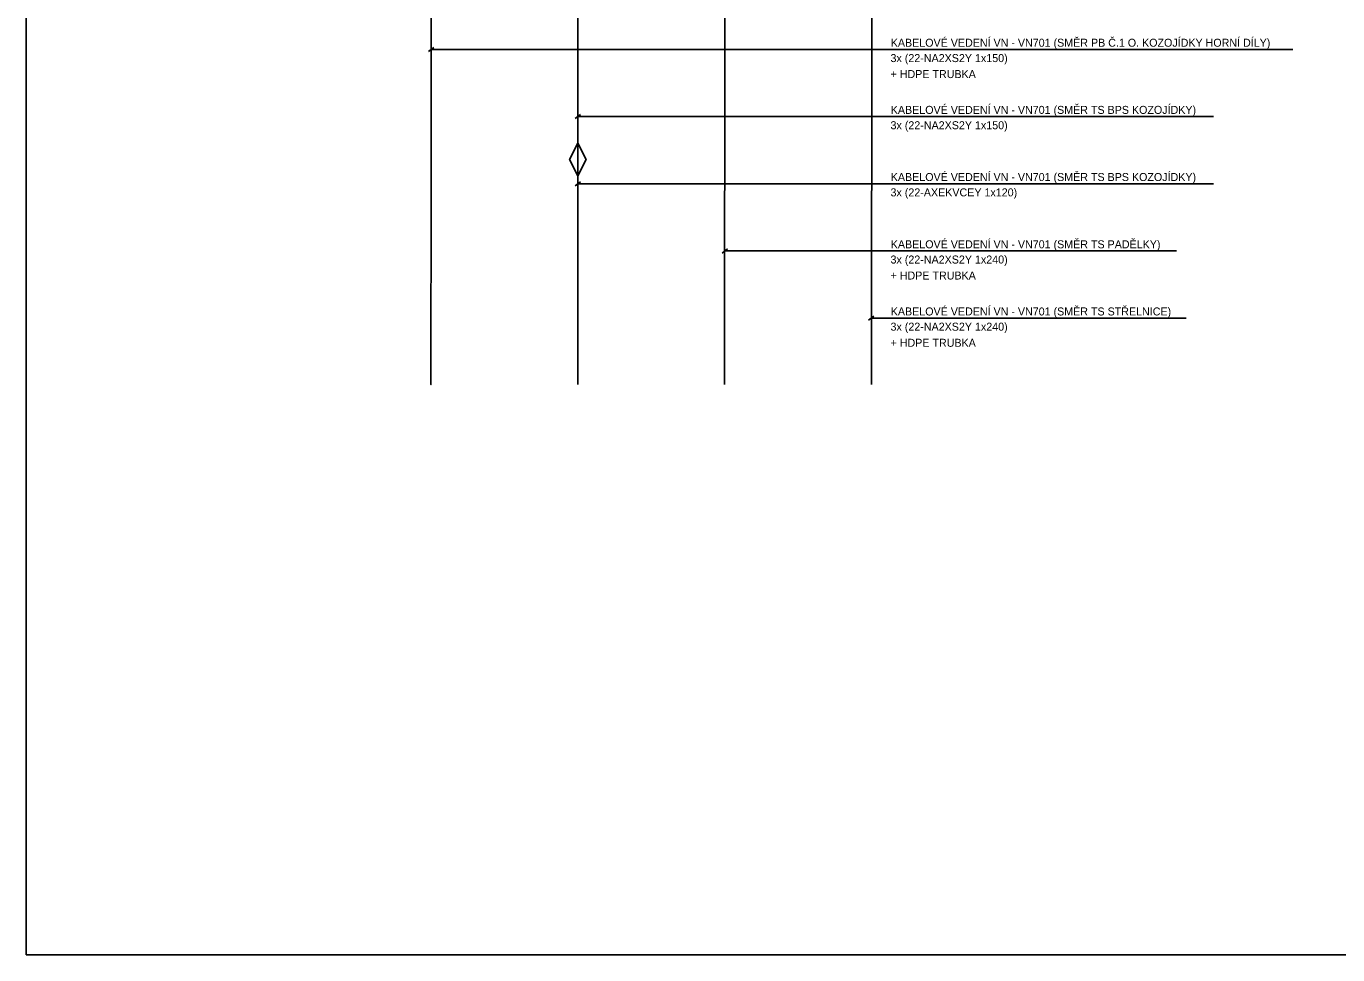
# Model space of a CAD drawing. Extents: x -540906 to -539838, y -1177786 to -1177461.
# Drawn here: x -540048 to -539943, y -1177785.8 to -1177711.4 of the extents above; entities that cross this region are included whole.
import ezdxf

# ---------------------------------------------------------------- set-up
doc = ezdxf.new("R2010")
doc.units = 0
for name, color, linetype in [('Implicitní', 7, 'Continuous'), ('KAB_SPOJKA_VN', 7, 'Continuous'), ('Kabel-nový', 7, 'Continuous'), ('Popisky', 7, 'Continuous'), ('TEXT-NORMAL', 7, 'Continuous'), ('TEXT-TUČNÝ-eon', 7, 'Continuous')]:
    doc.layers.add(name, color=color, linetype=linetype)

msp = doc.modelspace()

# ---------------------------------------------------------------- linework, layer by layer
at = {"layer": 'Implicitní'}
msp.add_lwpolyline([(-540047.95, -1177637.3), (-539837.95, -1177637.3), (-539837.95, -1177785.8), (-540047.95, -1177785.8)], close=True, dxfattribs=at)
at = {"layer": 'KAB_SPOJKA_VN'}
msp.add_lwpolyline([(-540003.79, -1177723.4), (-540004.45, -1177722.08), (-540003.79, -1177720.77), (-540003.13, -1177722.08)], close=True, dxfattribs=at)
at = {"layer": 'Kabel-nový'}
msp.add_lwpolyline([(-540015.53, -1177723.88), (-540015.56, -1177740.12), (-540015.56, -1177740.12)], dxfattribs=at)
at = {"layer": 'Popisky'}
for p, q in [((-540003.78, -1177704.05), (-540003.79, -1177722.08)), ((-539992.02, -1177704.05), (-539992.04, -1177740.12)), ((-539980.26, -1177704.05), (-539980.28, -1177740.12)), ((-540015.53, -1177704.15), (-540015.53, -1177723.88)), ((-540003.79, -1177722.08), (-540003.8, -1177740.12))]:
    msp.add_line(p, q, dxfattribs=at)
at = {"layer": 'TEXT-NORMAL'}
for p, q in [((-540015.74, -1177713.43), (-540015.32, -1177713.1)), ((-540015.53, -1177713.27), (-539946.54, -1177713.27)), ((-540004, -1177718.81), (-540003.58, -1177718.48)), ((-540003.79, -1177718.65), (-539952.89, -1177718.65)), ((-540004, -1177724.19), (-540003.58, -1177723.87)), ((-540003.79, -1177724.03), (-539952.89, -1177724.03)), ((-539992.24, -1177729.58), (-539991.82, -1177729.25)), ((-539992.03, -1177729.41), (-539955.87, -1177729.41)), ((-539980.51, -1177734.96), (-539980.1, -1177734.63)), ((-539980.3, -1177734.79), (-539955.09, -1177734.79))]:
    msp.add_line(p, q, dxfattribs=at)

# ---------------------------------------------------------------- texts
for s, p in [('3x (22-NA2XS2Y 1x150)', (-539978.76, -1177714.28)), ('+ HDPE TRUBKA', (-539978.76, -1177715.56)), ('3x (22-NA2XS2Y 1x150)', (-539978.76, -1177719.66)), ('3x (22-AXEKVCEY 1x120)', (-539978.76, -1177725.04)), ('3x (22-NA2XS2Y 1x240)', (-539978.76, -1177730.42)), ('+ HDPE TRUBKA', (-539978.76, -1177731.7)), ('3x (22-NA2XS2Y 1x240)', (-539978.76, -1177735.8)), ('+ HDPE TRUBKA', (-539978.76, -1177737.09))]:
    msp.add_text(s, height=0.6406, dxfattribs=at).set_placement(p)
at = {"layer": 'TEXT-TUČNÝ-eon'}
for s, p in [('KABELOVÉ VEDENÍ VN - VN701 (SMĚR PB Č.1 O. KOZOJÍDKY HORNÍ DÍLY)', (-539978.74, -1177713.05)), ('KABELOVÉ VEDENÍ VN - VN701 (SMĚR TS BPS KOZOJÍDKY)', (-539978.74, -1177718.43)), ('KABELOVÉ VEDENÍ VN - VN701 (SMĚR TS BPS KOZOJÍDKY)', (-539978.74, -1177723.81)), ('KABELOVÉ VEDENÍ VN - VN701 (SMĚR TS PADĚLKY)', (-539978.74, -1177729.2)), ('KABELOVÉ VEDENÍ VN - VN701 (SMĚR TS STŘELNICE)', (-539978.74, -1177734.58))]:
    msp.add_text(s, height=0.64, dxfattribs=at).set_placement(p)

doc.saveas('drawing.dxf')
